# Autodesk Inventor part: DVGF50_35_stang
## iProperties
Created: 2010-04
Part Number: DVGF50_35_stang
Document SubType Name: Modeling
Designer: TB
Mass: 285.144 g
Surface Area: 348.48 cm^2
Volume: 285.144 cm^3
Density: 1 g/cm^3
Author: TB
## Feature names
1. Revolution1
2. Fillet1
3. Revolution2
4. Extrusion1
5. Extrusion2
6. Chamfer1
7. Extrusion4
8. Chamfer5
9. Chamfer6
